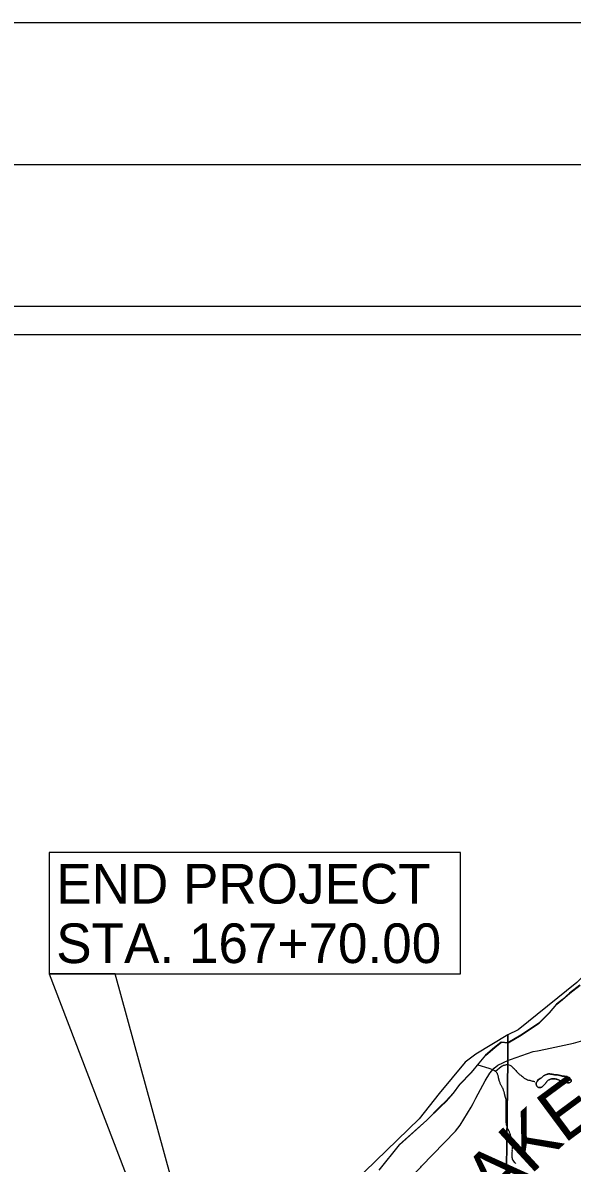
# Model space of a CAD drawing. Extents: x 0 to 34, y 0 to 22.
# Drawn here: x 4.217 to 6.155, y 17.975 to 22 of the extents above; entities that cross this region are included whole.
import ezdxf

# ---------------------------------------------------------------- set-up
doc = ezdxf.new("R2010")
doc.units = 0
for name, color, linetype in [('Default', 7, 'Continuous'), ('GM_X_Corporation', 7, 'Continuous'), ('GM_X_County_Text', 7, 'Continuous'), ('GM_X_Major_Lake', 7, 'Continuous'), ('GM_X_Minor_Lake', 7, 'Continuous'), ('GM_X_Minor_River', 7, 'Continuous'), ('GM_X_State_Route', 7, 'Continuous'), ('SH_Border', 7, 'Continuous'), ('SH_Cut_Line', 7, 'Continuous'), ('SH_Data', 7, 'Continuous'), ('SH_Text', 7, 'Continuous')]:
    doc.layers.add(name, color=color, linetype=linetype)

msp = doc.modelspace()

# ---------------------------------------------------------------- linework, layer by layer
at = {"layer": 'Default'}
msp.add_line((1.5, 21.5), (32, 21.5), dxfattribs=at)
at = {"layer": 'GM_X_Corporation'}
for points in [[(6.9502, 17.5872), (6.9579, 18.132), (6.9678, 18.7128), (6.9757, 18.7441), (6.9797, 18.9177), (6.9785, 19.0928), (6.982, 19.1525), (6.9801, 19.32), (6.853, 19.2258), (6.8192, 19.1935), (6.7498, 19.1303), (6.6516, 19.0408), (6.5511, 18.9721), (6.5041, 18.9408), (6.4162, 18.8547), (6.3769, 18.8098), (6.2533, 18.6952), (6.1715, 18.6122), (5.9643, 18.4453), (5.9276, 18.4276), (5.9278, 18.3408), (5.912, 16.9809)], [(6.1818, 18.6027), (6.1462, 18.5745), (6.1205, 18.552), (6.1002, 18.5358), (6.0744, 18.5057), (6.0371, 18.4684), (5.9736, 18.4264), (5.9285, 18.3999), (5.9042, 18.4013), (5.8816, 18.3829), (5.8498, 18.3554), (5.8256, 18.3279), (5.7986, 18.2943), (5.7571, 18.2525), (5.7351, 18.2216), (5.7098, 18.1929), (5.6894, 18.1741), (5.6418, 18.1263), (5.5444, 18.0394), (5.4735, 17.9496)], [(6.1818, 18.6027), (6.1462, 18.5745), (6.1205, 18.552), (6.1002, 18.5358), (6.0744, 18.5057), (6.0371, 18.4684), (5.9736, 18.4264), (5.9285, 18.3999), (5.9042, 18.4013), (5.8816, 18.3829), (5.8498, 18.3554), (5.8256, 18.3279), (5.7986, 18.2943), (5.7571, 18.2525), (5.7351, 18.2216), (5.7098, 18.1929), (5.6894, 18.1741), (5.6418, 18.1263), (5.5444, 18.0394), (5.4735, 17.9496)], [(5.912, 16.9809), (5.9278, 18.3408), (5.9276, 18.4276), (5.8148, 18.3594), (5.7778, 18.3311), (5.6854, 18.2203), (5.6148, 18.1311), (5.3086, 17.8335)]]:
    msp.add_lwpolyline(points, dxfattribs=at)
at = {"layer": 'GM_X_Major_Lake'}
msp.add_lwpolyline([(5.4746, 17.9495), (5.5454, 18.0393), (5.6429, 18.1262), (5.6905, 18.174), (5.7108, 18.1928), (5.7362, 18.2215), (5.7582, 18.2525), (5.7997, 18.2943), (5.8266, 18.3279), (5.8509, 18.3554), (5.8827, 18.3828), (5.9053, 18.4012), (5.9296, 18.3998), (5.9747, 18.4264), (6.0382, 18.4683), (6.0755, 18.5056), (6.1012, 18.5358), (6.1215, 18.5519), (6.1472, 18.5745), (6.1829, 18.6026)], dxfattribs=at)
msp.add_lwpolyline([(5.4746, 17.9495), (5.5454, 18.0393), (5.6429, 18.1262), (5.6905, 18.174), (5.7108, 18.1928), (5.7362, 18.2215), (5.7582, 18.2525), (5.7997, 18.2943), (5.8266, 18.3279), (5.8509, 18.3554), (5.8827, 18.3828), (5.9053, 18.4012), (5.9296, 18.3998), (5.9747, 18.4264), (6.0382, 18.4683), (6.0755, 18.5056), (6.1012, 18.5358), (6.1215, 18.5519), (6.1472, 18.5745), (6.1829, 18.6026)], dxfattribs=at)
at = {"layer": 'GM_X_Minor_Lake'}
for points in [[(6.029, 18.2486), (6.0305, 18.2464), (6.0325, 18.2441), (6.0344, 18.243), (6.0363, 18.2422), (6.0382, 18.2419), (6.042, 18.2415), (6.0442, 18.2419), (6.0465, 18.2427), (6.0484, 18.2431), (6.0518, 18.2462), (6.054, 18.2485), (6.0567, 18.2516), (6.0585, 18.2535), (6.0604, 18.2558), (6.0623, 18.2585), (6.0642, 18.2608), (6.066, 18.2631), (6.0675, 18.265), (6.0709, 18.2677), (6.0739, 18.2689), (6.0762, 18.27), (6.0788, 18.2712), (6.0819, 18.2724), (6.0845, 18.2728), (6.0864, 18.2728), (6.0887, 18.2725), (6.091, 18.2725), (6.0929, 18.2721), (6.0952, 18.2718), (6.0982, 18.271), (6.1005, 18.2707), (6.1089, 18.2677), (6.1115, 18.2666), (6.115, 18.2655), (6.1176, 18.2644), (6.1195, 18.2632), (6.123, 18.2621), (6.1256, 18.2614), (6.1291, 18.2603), (6.1321, 18.2596), (6.134, 18.2592), (6.1367, 18.2589), (6.139, 18.2585), (6.142, 18.2581), (6.1443, 18.2585), (6.1473, 18.2593), (6.1496, 18.2605), (6.1514, 18.2632), (6.1514, 18.2655), (6.151, 18.2689), (6.1494, 18.2712), (6.1471, 18.2738), (6.1441, 18.2768), (6.1414, 18.2783), (6.1357, 18.2798), (6.1323, 18.2801), (6.1296, 18.2809), (6.1277, 18.2812), (6.1247, 18.2816), (6.122, 18.2819), (6.1201, 18.2823), (6.1182, 18.283), (6.1163, 18.2834), (6.114, 18.2841), (6.1117, 18.2845), (6.1094, 18.2848), (6.1068, 18.2856), (6.1037, 18.2863), (6.1014, 18.2867), (6.098, 18.287), (6.0957, 18.287), (6.0931, 18.287), (6.0904, 18.2873), (6.087, 18.2877), (6.0843, 18.2884), (6.0821, 18.2888), (6.0802, 18.2891), (6.0783, 18.2891), (6.0764, 18.2895), (6.0745, 18.2894), (6.071, 18.2894), (6.0692, 18.289), (6.0673, 18.2886), (6.0642, 18.2878), (6.0612, 18.2866), (6.0586, 18.2855), (6.0559, 18.2839), (6.054, 18.2828), (6.0522, 18.2816), (6.0499, 18.2789), (6.0465, 18.2762), (6.0439, 18.2747), (6.0416, 18.2731), (6.039, 18.2712), (6.0356, 18.2685), (6.0333, 18.2658), (6.0311, 18.2631), (6.03, 18.2612)], [(6.03, 18.2612), (6.0304, 18.262), (6.03, 18.2612), (6.0311, 18.2631), (6.0333, 18.2658), (6.0356, 18.2685), (6.039, 18.2712), (6.0416, 18.2731), (6.0439, 18.2747), (6.0465, 18.2762), (6.0499, 18.2789), (6.0522, 18.2816), (6.054, 18.2828), (6.0559, 18.2839), (6.0586, 18.2855), (6.0612, 18.2866), (6.0642, 18.2878), (6.0673, 18.2886), (6.0692, 18.289), (6.071, 18.2894), (6.0745, 18.2894), (6.0764, 18.2895), (6.0783, 18.2891), (6.0802, 18.2891), (6.0821, 18.2888), (6.0843, 18.2884), (6.087, 18.2877), (6.0904, 18.2873), (6.0931, 18.287), (6.0957, 18.287), (6.098, 18.287), (6.1014, 18.2867), (6.1037, 18.2863), (6.1068, 18.2856), (6.1094, 18.2848), (6.1117, 18.2845), (6.114, 18.2841), (6.1163, 18.2834), (6.1182, 18.283), (6.1201, 18.2823), (6.122, 18.2819), (6.1247, 18.2816), (6.1277, 18.2812), (6.1296, 18.2809), (6.1323, 18.2801), (6.1357, 18.2798), (6.1414, 18.2783), (6.1441, 18.2768), (6.1471, 18.2738), (6.1494, 18.2712), (6.151, 18.2689), (6.1514, 18.2655), (6.1514, 18.2632), (6.1496, 18.2605), (6.1473, 18.2593), (6.1443, 18.2585), (6.142, 18.2581), (6.139, 18.2585), (6.1367, 18.2589), (6.134, 18.2592), (6.1321, 18.2596), (6.1291, 18.2603), (6.1256, 18.2614), (6.123, 18.2621), (6.1195, 18.2632), (6.1176, 18.2644), (6.115, 18.2655), (6.1115, 18.2666), (6.1089, 18.2677), (6.1005, 18.2707), (6.0982, 18.271), (6.0952, 18.2718), (6.0929, 18.2721), (6.091, 18.2725), (6.0887, 18.2725), (6.0864, 18.2728), (6.0845, 18.2728), (6.0819, 18.2724), (6.0788, 18.2712), (6.0762, 18.27), (6.0739, 18.2689), (6.0709, 18.2677), (6.0675, 18.265), (6.066, 18.2631), (6.0642, 18.2608), (6.0623, 18.2585), (6.0604, 18.2558), (6.0585, 18.2535), (6.0567, 18.2516), (6.054, 18.2485), (6.0518, 18.2462), (6.0484, 18.2431), (6.0465, 18.2427), (6.0442, 18.2419), (6.042, 18.2415), (6.0382, 18.2419), (6.0363, 18.2422), (6.0344, 18.243), (6.0325, 18.2441), (6.0305, 18.2464), (6.029, 18.2486)], [(6.029, 18.2486), (6.0285, 18.254), (6.0285, 18.2566), (6.0296, 18.2601), (6.0311, 18.262)], [(6.03, 18.2612), (6.0285, 18.2566), (6.0285, 18.254), (6.029, 18.2486)]]:
    msp.add_lwpolyline(points, dxfattribs=at)
at = {"layer": 'GM_X_Minor_River'}
for points in [[(5.822, 18.3218), (5.8605, 18.3094), (5.8643, 18.3083), (5.8701, 18.3064), (5.8731, 18.3053), (5.8758, 18.3042), (5.8781, 18.3035), (5.8811, 18.3016), (5.8842, 18.2993), (5.8865, 18.2971), (5.8884, 18.2944), (5.89, 18.2918), (5.8907, 18.2895), (5.8915, 18.2872), (5.8923, 18.285), (5.8927, 18.2827), (5.8935, 18.2804), (5.8939, 18.2785), (5.8943, 18.2766), (5.8951, 18.2732), (5.8955, 18.2713), (5.8963, 18.2694), (5.8967, 18.2675), (5.8975, 18.2645), (5.8983, 18.2618), (5.8994, 18.2591), (5.9002, 18.2569), (5.9014, 18.2546), (5.9022, 18.2527), (5.9029, 18.2508), (5.9041, 18.2489), (5.906, 18.2459), (5.9068, 18.244), (5.908, 18.2421), (5.9088, 18.2402), (5.9103, 18.2368), (5.9111, 18.2345), (5.9119, 18.2322), (5.9127, 18.23), (5.9134, 18.2281), (5.9142, 18.2262), (5.9146, 18.2235), (5.9154, 18.2205), (5.919, 18.208), (5.9198, 18.2042), (5.9206, 18.2007), (5.921, 18.1973), (5.921, 18.1946), (5.9211, 18.1924), (5.9211, 18.1901), (5.9211, 18.187), (5.9212, 18.1832), (5.9212, 18.1798), (5.9209, 18.1745), (5.9209, 18.1703), (5.921, 18.1669), (5.921, 18.1642), (5.921, 18.1619), (5.921, 18.1596), (5.9211, 18.1573), (5.9211, 18.1551), (5.9211, 18.1524), (5.9212, 18.1494), (5.9212, 18.1463), (5.9212, 18.1433), (5.9209, 18.1398), (5.9209, 18.1364), (5.921, 18.1326), (5.921, 18.128), (5.9211, 18.1242), (5.9215, 18.1208), (5.9215, 18.1181), (5.9219, 18.1155), (5.9223, 18.1132), (5.9227, 18.1113), (5.9235, 18.1071), (5.9243, 18.1052), (5.9255, 18.1026), (5.9263, 18.0999), (5.9274, 18.0973), (5.9282, 18.0954), (5.9294, 18.0935), (5.9306, 18.0904), (5.9313, 18.0885), (5.9325, 18.0863), (5.9333, 18.0836), (5.9348, 18.0798), (5.936, 18.0768), (5.9368, 18.0737), (5.9376, 18.0711), (5.9388, 18.0681), (5.9412, 18.0589), (5.9416, 18.0559), (5.9424, 18.0529), (5.9428, 18.0502), (5.9432, 18.0472), (5.9436, 18.0449)], [(5.8842, 18.2993), (5.9045, 18.3163), (5.9075, 18.3179), (5.9098, 18.3186), (5.9132, 18.3202), (5.9158, 18.321), (5.9192, 18.3218), (5.9215, 18.3222), (5.9238, 18.3226), (5.926, 18.3226), (5.9279, 18.323), (5.9298, 18.323), (5.9356, 18.3204), (5.9375, 18.3193), (5.9402, 18.3178), (5.9424, 18.3163), (5.9451, 18.3137), (5.9474, 18.311), (5.9501, 18.3088), (5.952, 18.3065), (5.9544, 18.3039), (5.9563, 18.3012), (5.959, 18.2978), (5.9605, 18.2959), (5.964, 18.2918), (5.967, 18.2899), (5.9689, 18.2884), (5.9709, 18.2869), (5.9735, 18.285), (5.9766, 18.2828), (5.98, 18.2801), (5.9831, 18.2775), (5.9858, 18.2752), (5.9881, 18.2737), (5.9904, 18.2726), (5.9923, 18.2715), (5.9942, 18.2708), (5.9976, 18.2693), (6.0011, 18.2682), (6.0052, 18.2671), (6.0079, 18.2659), (6.0113, 18.2652), (6.0132, 18.2649), (6.0151, 18.2641), (6.0182, 18.2638), (6.0205, 18.2634), (6.0224, 18.263), (6.0228, 18.263)], [(5.9436, 18.0449), (5.9436, 18.0422), (5.944, 18.0392), (5.9437, 18.0365), (5.9437, 18.0338), (5.9434, 18.0316), (5.9434, 18.0293), (5.943, 18.0266), (5.9431, 18.0243), (5.9427, 18.0217), (5.9428, 18.0178), (5.9424, 18.0129), (5.9421, 18.0091), (5.9421, 18.006), (5.9422, 18.0034), (5.9422, 18.0011), (5.9426, 17.9984), (5.9426, 17.9954), (5.943, 17.9927), (5.9434, 17.9904), (5.9446, 17.9866), (5.9454, 17.9847), (5.9477, 17.9817), (5.95, 17.9787), (5.9519, 17.9772), (5.9535, 17.9753), (5.9554, 17.9738)]]:
    msp.add_lwpolyline(points, dxfattribs=at)
at = {"layer": 'GM_X_State_Route'}
for points in [[(6.0326, 18.3714), (6.0607, 18.3774), (6.1592, 18.3982), (6.2087, 18.4126), (6.218, 18.4153), (6.2484, 18.4247), (6.2999, 18.4406), (6.3436, 18.4542), (6.3878, 18.4684)], [(5.937, 18.3409), (6.018, 18.3683), (6.0326, 18.3714)], [(5.8056, 18.1847), (5.8155, 18.2035), (5.8481, 18.2653), (5.8649, 18.2925), (5.8798, 18.3094), (5.8926, 18.32), (5.9303, 18.3386), (5.937, 18.3409)], [(5.163, 17.4993), (5.2208, 17.5572), (5.3722, 17.7088), (5.3771, 17.7136), (5.5209, 17.8566), (5.5553, 17.8909), (5.5592, 17.895), (5.5864, 17.924), (5.6209, 17.9608), (5.6236, 17.9637), (5.7433, 18.0872), (5.7594, 18.1087), (5.799, 18.1721), (5.8056, 18.1847)]]:
    msp.add_lwpolyline(points, dxfattribs=at)
at = {"layer": 'SH_Border'}
for points in [[(1.5, 21.5), (33.5, 21.5), (33.5, 0.5), (1.5, 0.5)], [(4.3095, 18.6434), (5.7614, 18.6434), (5.7614, 19.0717), (4.3095, 19.0717)]]:
    msp.add_lwpolyline(points, close=True, dxfattribs=at)
at = {"layer": 'SH_Cut_Line'}
msp.add_lwpolyline([(0, 0), (34, 0), (34, 22), (0, 22)], close=True, dxfattribs=at)
at = {"layer": 'SH_Data'}
for p, q in [((2, 21), (9, 21)), ((2.1, 20.9), (8.9, 20.9))]:
    msp.add_line(p, q, dxfattribs=at)
at = {"layer": 'SH_Text'}
msp.add_lwpolyline([(4.3095, 18.6434), (5.1284, 16.5056), (4.5432, 18.6434)], close=True, dxfattribs=at)

# ---------------------------------------------------------------- texts
at = {"layer": 'GM_X_County_Text'}
for s, rotation, p in [('E', 36.5386, (6.1264, 18.0412)), ('K', 42.6441, (6.0074, 17.9311)), ('A', 45.2918, (5.8912, 17.8137))]:
    msp.add_text(s, height=0.1894, rotation=rotation, dxfattribs=at).set_placement(p)
at = {"layer": 'SH_Text'}
for s, p in [('END PROJECT', (4.3349, 18.8909)), ('STA. 167+70.00  ', (4.3349, 18.6809))]:
    msp.add_text(s, height=0.14, dxfattribs=at).set_placement(p)

doc.saveas('drawing.dxf')
